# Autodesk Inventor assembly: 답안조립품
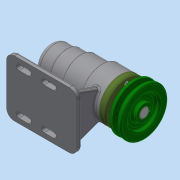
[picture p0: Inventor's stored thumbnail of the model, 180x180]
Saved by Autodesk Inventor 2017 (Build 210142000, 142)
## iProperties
Part Number: 답안조립품
Material: 일반
Document SubType Name: Assembly
Designer: MRC
Author: MRC
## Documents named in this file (12)
- C:\Users\MRC\Desktop\711009V1009\답안조립품.iam
- C:\Users\MRC\Desktop\711009V1009\본체.ipt
- C:\Users\MRC\Desktop\711009V1009\V벨트풀리.ipt
- C:\Users\MRC\Desktop\711009V1009\멈춤나사 M3.ipt
- C:\Users\MRC\Desktop\711009V1009\베어링 6004.ipt
- C:\Users\MRC\Desktop\711009V1009\베어링 51202.ipt
- C:\Users\MRC\Desktop\711009V1009\볼트 M4.ipt
- C:\Users\MRC\Desktop\711009V1009\어댑터슬리브.ipt
- C:\Users\MRC\Desktop\711009V1009\오일 실 20x35x7.ipt
- C:\Users\MRC\Desktop\711009V1009\축.ipt
- C:\Users\MRC\Desktop\711009V1009\커버.ipt
- C:\Users\MRC\Desktop\711009V1009\키 5x5.ipt
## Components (1 placed, 1 different names)
1. V벨트풀리:1 — 플러쉬:2
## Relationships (1: Flush 1)
- 플러쉬:2 [Flush]: V벨트풀리:1
